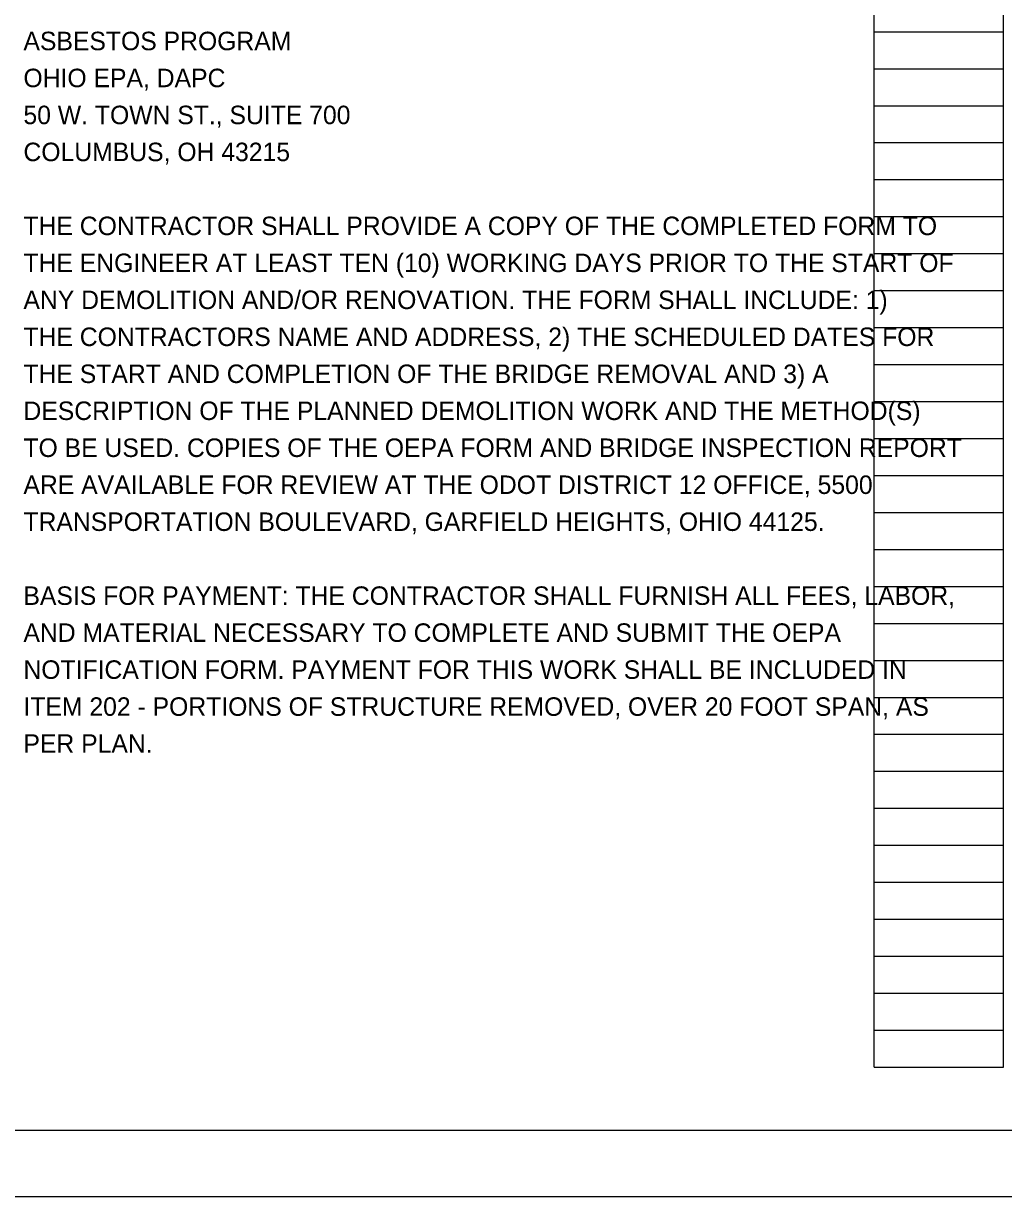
# Model space of a CAD drawing. Extents: x 0 to 34, y 0 to 22.
# Drawn here: x 17.24 to 24.66, y 0 to 8.88 of the extents above; entities that cross this region are included whole.
import ezdxf

# ---------------------------------------------------------------- set-up
doc = ezdxf.new("R2010")
doc.units = 0
for name, color, linetype in [('SH_Border', 7, 'Continuous'), ('SH_Cut_Line', 7, 'Continuous'), ('SH_Data', 7, 'Continuous'), ('SH_Text', 7, 'Continuous')]:
    doc.layers.add(name, color=color, linetype=linetype)

msp = doc.modelspace()

# ---------------------------------------------------------------- linework, layer by layer
at = {"layer": 'SH_Border'}
msp.add_lwpolyline([(1.5, 21.5), (33.5, 21.5), (33.5, 0.5), (1.5, 0.5)], close=True, dxfattribs=at)
at = {"layer": 'SH_Cut_Line'}
msp.add_lwpolyline([(0, 0), (34, 0), (34, 22), (0, 22)], close=True, dxfattribs=at)
at = {"layer": 'SH_Data'}
for p, q in [((23.68, 0.98), (23.68, 21.14)), ((24.66, 0.98), (24.66, 21.14)), ((23.68, 8.82), (24.66, 8.82)), ((23.68, 8.54), (24.66, 8.54)), ((23.68, 8.26), (24.66, 8.26)), ((23.68, 7.98), (24.66, 7.98)), ((23.68, 7.7), (24.66, 7.7)), ((23.68, 7.42), (24.66, 7.42)), ((23.68, 7.14), (24.66, 7.14)), ((23.68, 6.86), (24.66, 6.86)), ((23.68, 6.58), (24.66, 6.58)), ((23.68, 6.3), (24.66, 6.3)), ((23.68, 6.02), (24.66, 6.02)), ((23.68, 5.74), (24.66, 5.74)), ((23.68, 5.46), (24.66, 5.46)), ((23.68, 5.18), (24.66, 5.18)), ((23.68, 4.9), (24.66, 4.9)), ((23.68, 4.62), (24.66, 4.62)), ((23.68, 4.34), (24.66, 4.34)), ((23.68, 4.06), (24.66, 4.06)), ((23.68, 3.78), (24.66, 3.78)), ((23.68, 3.5), (24.66, 3.5)), ((23.68, 3.22), (24.66, 3.22)), ((23.68, 2.94), (24.66, 2.94)), ((23.68, 2.66), (24.66, 2.66)), ((23.68, 2.38), (24.66, 2.38)), ((23.68, 2.1), (24.66, 2.1)), ((23.68, 1.82), (24.66, 1.82)), ((23.68, 1.54), (24.66, 1.54)), ((23.68, 1.26), (24.66, 1.26)), ((23.68, 0.98), (24.66, 0.98))]:
    msp.add_line(p, q, dxfattribs=at)

# ---------------------------------------------------------------- texts
at = {"layer": 'SH_Text'}
for s, p in [('ASBESTOS PROGRAM ', (17.24, 8.68)), ('OHIO EPA, DAPC ', (17.24, 8.4)), ('50 W. TOWN ST., SUITE 700 ', (17.24, 8.12)), ('COLUMBUS, OH 43215', (17.24, 7.84)), ('THE CONTRACTOR SHALL PROVIDE A COPY OF THE COMPLETED FORM TO ', (17.24, 7.28)), ('THE ENGINEER AT LEAST TEN (10) WORKING DAYS PRIOR TO THE START OF ', (17.24, 7)), ('ANY DEMOLITION AND/OR RENOVATION. THE FORM SHALL INCLUDE: 1) ', (17.24, 6.72)), ('THE CONTRACTORS NAME AND ADDRESS, 2) THE SCHEDULED DATES FOR ', (17.24, 6.44)), ('THE START AND COMPLETION OF THE BRIDGE REMOVAL AND 3) A ', (17.24, 6.16)), ('DESCRIPTION OF THE PLANNED DEMOLITION WORK AND THE METHOD(S) ', (17.24, 5.88)), ('TO BE USED. COPIES OF THE OEPA FORM AND BRIDGE INSPECTION REPORT ', (17.24, 5.6)), ('ARE AVAILABLE FOR REVIEW AT THE ODOT DISTRICT 12 OFFICE, 5500 ', (17.24, 5.32)), ('TRANSPORTATION BOULEVARD, GARFIELD HEIGHTS, OHIO 44125. ', (17.24, 5.04)), ('BASIS FOR PAYMENT: THE CONTRACTOR SHALL FURNISH ALL FEES, LABOR, ', (17.24, 4.48)), ('AND MATERIAL NECESSARY TO COMPLETE AND SUBMIT THE OEPA ', (17.24, 4.2)), ('NOTIFICATION FORM. PAYMENT FOR THIS WORK SHALL BE INCLUDED IN ', (17.24, 3.92)), ('ITEM 202 - PORTIONS OF STRUCTURE REMOVED, OVER 20 FOOT SPAN, AS ', (17.24, 3.64)), ('PER PLAN.', (17.24, 3.36))]:
    msp.add_text(s, height=0.14, dxfattribs=at).set_placement(p)

doc.saveas('drawing.dxf')
